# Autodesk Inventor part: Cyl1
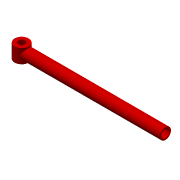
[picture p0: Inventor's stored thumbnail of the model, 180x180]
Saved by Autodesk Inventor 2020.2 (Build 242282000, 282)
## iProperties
Created: 2005-10
Part Number: Cyl1
Document SubType Name: Modeling
Designer: F.Stasiak
Density: 1 g/cm^3
Material: Ogólny
Appearance: Czerwony
Manager: www.cadconsulting.pl
Company: Fabian Stasiak CAD Consulting
Author: F.Stasiak
Subject: Zbiór ćwiczeń. Autodesk Inventor 2020. Kurs podstawowy
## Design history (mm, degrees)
sketch "Szkic1"
  geometry: L1 (702.039, -163.908)-(-322.961, -163.908); L2 (-322.961, -163.908)-(-322.961, -203.908); L3 (-322.961, -203.908)-(702.039, -203.908); L4 (702.039, -203.908)-(702.039, -163.908); C1 r 50 at (-322.961, -163.908); C2 r 25 at (-322.961, -163.908)
  constraints: 8 end point, 2 centre point, 2 coincident, 2 parallel, 1 horizontal, 1 perpendicular
  dimensions: "d0" = 1025 distance of L2.end L3.end; "d1" = 40 distance of L3.end L1.start; "d3" = 100 diameter of C1; "d4" = 50 diameter of C2
revolve "Obrót1" stored, may be unused: angle "d5" = 90 deg
extrude "Wyciągnięcie proste1" join sketch "Szkic1" stored distance "d6" = 100; taper "d7" = 0 deg
extrude "Wyciągnięcie proste2" cut sketch "Szkic1" extent not by distance; stored distance "d8" = 300; taper "d9" = 0 deg
sketch "Szkic2"
  geometry: C1 r 40 at (0, 0) reference; C2 r 30 at (0, 0)
  constraints: 1 centre point, 1 coincident
  dimensions: "d10" = 60 diameter of C2
extrude "Wyciągnięcie proste3" cut sketch "Szkic2" distance "d11" = 500; taper "d12" = 0 deg
node "Bryła1"
node "Korpusy bryłowe"
node "Korpusy powierzchniowe"
